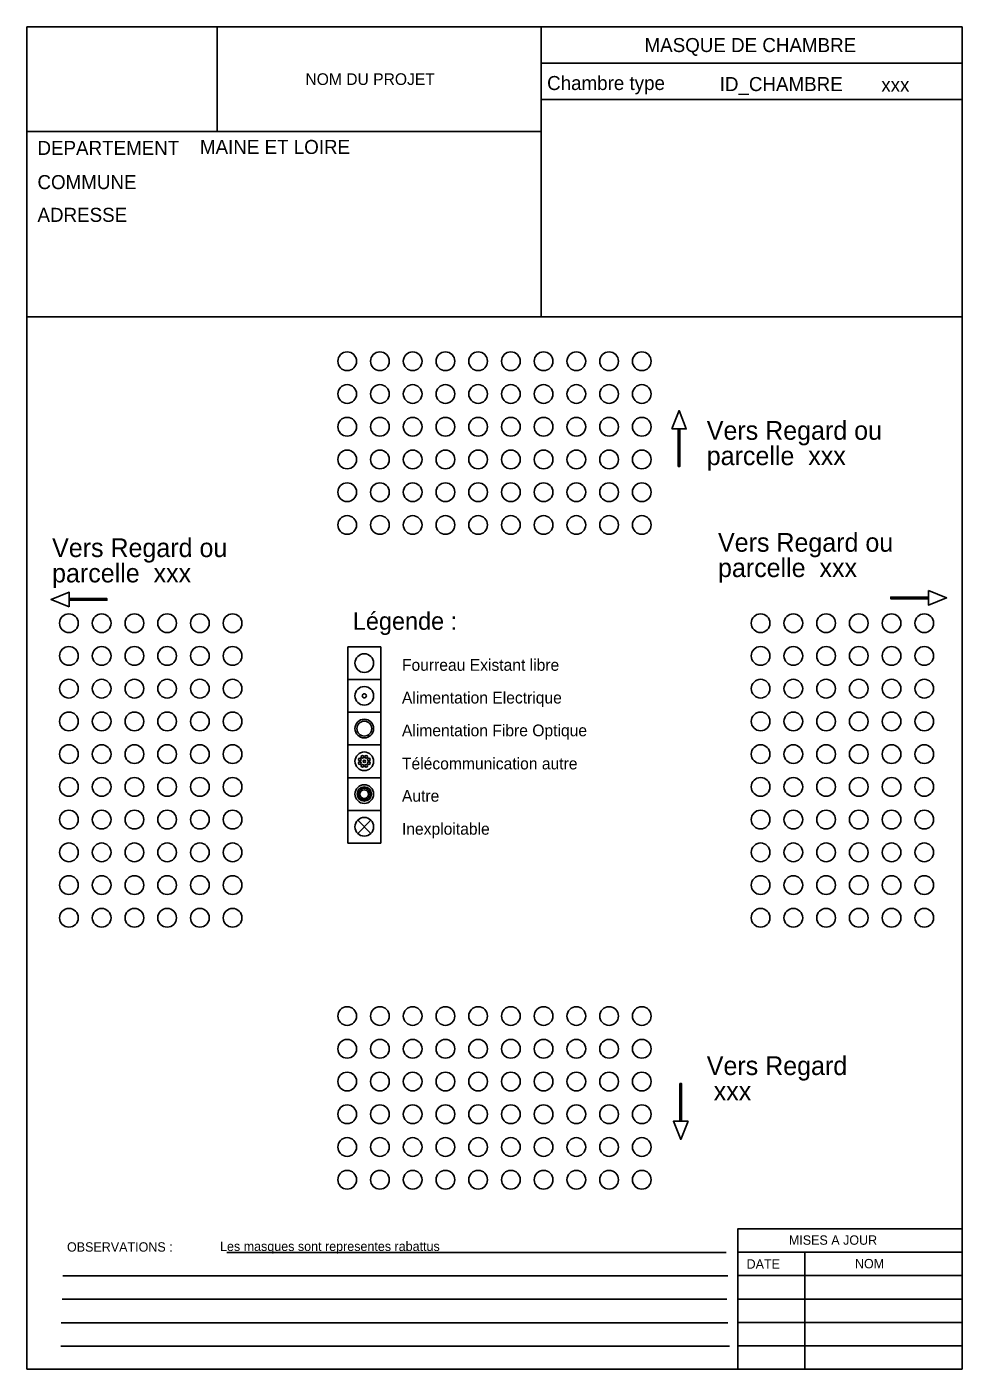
# Model space of a CAD drawing. Extents: x 10574.2 to 10614.2, y 48193.4 to 48250.8.
import ezdxf

# ---------------------------------------------------------------- set-up
doc = ezdxf.new("R2010")
doc.units = 0
doc.layers.add('GCV-détails', color=7, linetype='Continuous')

# ---------------------------------------------------------------- blocks, each defined once
blk = doc.blocks.new('Fourreau existant libre')
at = {"layer": 'GCV-détails'}
for p, q in [((0.7, 0.7), (-0.7, 0.7)), ((-0.7, 0.7), (-0.7, -0.7)), ((0.7, -0.7), (0.7, 0.7)), ((0.7, 0.7), (0.7, 0.7)), ((-0.7, -0.7), (0.7, -0.7))]:
    blk.add_line(p, q, dxfattribs=at)
blk.add_circle((0, 0), 0.4, dxfattribs=at)
blk = doc.blocks.new('Alimentation Fibre optique')
at = {"layer": 'GCV-détails'}
for p, q in [((0.7, 0.7), (-0.7, 0.7)), ((-0.7, 0.7), (-0.7, -0.7)), ((0.7, -0.7), (0.7, 0.7)), ((0.7, 0.7), (0.7, 0.7)), ((-0.7, -0.7), (0.7, -0.7))]:
    blk.add_line(p, q, dxfattribs=at)
for radius in [0.4, 0.318]:
    blk.add_circle((0, 0), radius, dxfattribs=at)
blk = doc.blocks.new('Alimentation Electrique')
at = {"layer": 'GCV-détails'}
for p, q in [((0.7, 0.7), (-0.7, 0.7)), ((-0.7, 0.7), (-0.7, -0.7)), ((0.7, -0.7), (0.7, 0.7)), ((0.7, 0.7), (0.7, 0.7)), ((-0.7, -0.7), (0.7, -0.7))]:
    blk.add_line(p, q, dxfattribs=at)
for radius in [0.4, 0.0885]:
    blk.add_circle((0, 0), radius, dxfattribs=at)
blk = doc.blocks.new('télécommunication autre')
at = {"layer": 'GCV-détails'}
for p, q in [((0.7, 0.7), (-0.7, 0.7)), ((-0.7, 0.7), (-0.7, -0.7)), ((0.7, -0.7), (0.7, 0.7)), ((0.7, 0.7), (0.7, 0.7)), ((-0.7, -0.7), (0.7, -0.7))]:
    blk.add_line(p, q, dxfattribs=at)
for centre, radius in [((0, 0), 0.4), ((-0.192, 0.079), 0.0541), ((-0.079, 0.192), 0.0541), ((0, 0), 0.0541), ((0.079, 0.192), 0.0541), ((0.192, 0.079), 0.0541), ((-0.192, -0.079), 0.0541), ((-0.079, -0.192), 0.0541), ((0.079, -0.192), 0.0541), ((0.192, -0.079), 0.0541)]:
    blk.add_circle(centre, radius, dxfattribs=at)
blk = doc.blocks.new('Autre')
at = {"layer": 'GCV-détails'}
for p, q in [((0.7, 0.7), (-0.7, 0.7)), ((-0.7, 0.7), (-0.7, -0.7)), ((0.7, -0.7), (0.7, 0.7)), ((0.7, 0.7), (0.7, 0.7)), ((-0.7, -0.7), (0.7, -0.7))]:
    blk.add_line(p, q, dxfattribs=at)
for radius in [0.4, 0.307, 0.251, 0.185]:
    blk.add_circle((0, 0), radius, dxfattribs=at)
blk = doc.blocks.new('Inexploitable')
at = {"layer": 'GCV-détails'}
for p, q in [((0.7, 0.7), (-0.7, 0.7)), ((-0.7, 0.7), (-0.7, -0.7)), ((0.7, -0.7), (0.7, 0.7)), ((0.7, 0.7), (0.7, 0.7)), ((-0.7, -0.7), (0.7, -0.7))]:
    blk.add_line(p, q, dxfattribs=at)
for points in [[(-0.283, 0.283), (0.283, -0.283)], [(-0.283, -0.283), (0.283, 0.283)]]:
    blk.add_lwpolyline(points, dxfattribs=at)
blk.add_circle((0, 0), 0.4, dxfattribs=at)
blk = doc.blocks.new('Fleche vers regard')
at = {"layer": 'GCV-détails'}
for points in [[(1.608, -0.036), (1.608, 0.036), (0, 0.036), (0, -0.036)], [(1.608, 0.312), (1.608, -0.312), (2.388, 0)]]:
    blk.add_lwpolyline(points, close=True, dxfattribs=at)

msp = doc.modelspace()

# ---------------------------------------------------------------- linework, layer by layer
at = {"layer": 'GCV-détails'}
for p, q in [((10607.507, 48193.396), (10607.507, 48198.396)), ((10604.283, 48194.384), (10575.691, 48194.384))]:
    msp.add_line(p, q, dxfattribs=at)
for points in [[(10574.233, 48193.396), (10614.233, 48193.396), (10614.233, 48250.796), (10574.233, 48250.796)], [(10582.366, 48246.323), (10596.233, 48246.323), (10596.233, 48250.796), (10582.366, 48250.796)], [(10596.233, 48249.24), (10614.233, 48249.24), (10614.233, 48250.796), (10596.233, 48250.796)], [(10596.233, 48238.396), (10614.233, 48238.396), (10614.233, 48249.24), (10596.233, 48249.24)], [(10596.233, 48247.684), (10614.233, 48247.684), (10614.233, 48249.24), (10596.233, 48249.24)], [(10574.233, 48238.396), (10596.233, 48238.396), (10596.233, 48246.323), (10574.233, 48246.323)], [(10604.633, 48193.396), (10614.233, 48193.396), (10614.233, 48199.396), (10604.633, 48199.396)]]:
    msp.add_lwpolyline(points, close=True, dxfattribs=at)
for points in [[(10582.783, 48198.384), (10604.137, 48198.384)], [(10604.633, 48198.396), (10614.233, 48198.396)], [(10575.775, 48197.384), (10604.175, 48197.384), (10604.211, 48197.384)], [(10604.633, 48197.396), (10614.233, 48197.396)], [(10575.741, 48196.384), (10604.175, 48196.384)], [(10604.633, 48196.396), (10614.233, 48196.396)], [(10575.705, 48195.384), (10604.211, 48195.384)], [(10604.633, 48195.396), (10604.633, 48195.396), (10614.233, 48195.396)], [(10604.633, 48194.396), (10614.233, 48194.396)]]:
    msp.add_lwpolyline(points, dxfattribs=at)
for centre in [(10587.933, 48236.496), (10589.333, 48236.496), (10590.733, 48236.496), (10592.133, 48236.496), (10593.533, 48236.496), (10594.933, 48236.496), (10596.333, 48236.496), (10597.733, 48236.496), (10599.133, 48236.496), (10600.533, 48236.496), (10587.933, 48235.096), (10589.333, 48235.096), (10590.733, 48235.096), (10592.133, 48235.096), (10593.533, 48235.096), (10594.933, 48235.096), (10596.333, 48235.096), (10597.733, 48235.096), (10599.133, 48235.096), (10600.533, 48235.096), (10587.933, 48233.696), (10589.333, 48233.696), (10590.733, 48233.696), (10592.133, 48233.696), (10593.533, 48233.696), (10594.933, 48233.696), (10596.333, 48233.696), (10597.733, 48233.696), (10599.133, 48233.696), (10600.533, 48233.696), (10587.933, 48232.296), (10589.333, 48232.296), (10590.733, 48232.296), (10592.133, 48232.296), (10593.533, 48232.296), (10594.933, 48232.296), (10596.333, 48232.296), (10597.733, 48232.296), (10599.133, 48232.296), (10600.533, 48232.296), (10587.933, 48230.896), (10589.333, 48230.896), (10590.733, 48230.896), (10592.133, 48230.896), (10593.533, 48230.896), (10594.933, 48230.896), (10596.333, 48230.896), (10597.733, 48230.896), (10599.133, 48230.896), (10600.533, 48230.896), (10587.933, 48229.496), (10589.333, 48229.496), (10590.733, 48229.496), (10592.133, 48229.496), (10593.533, 48229.496), (10594.933, 48229.496), (10596.333, 48229.496), (10597.733, 48229.496), (10599.133, 48229.496), (10600.533, 48229.496), (10576.033, 48225.296), (10577.433, 48225.296), (10578.833, 48225.296), (10580.233, 48225.296), (10581.633, 48225.296), (10583.033, 48225.296), (10605.614, 48225.296), (10607.014, 48225.296), (10608.414, 48225.296), (10609.814, 48225.296), (10611.214, 48225.296), (10612.614, 48225.296), (10576.033, 48223.896), (10577.433, 48223.896), (10578.833, 48223.896), (10580.233, 48223.896), (10581.633, 48223.896), (10583.033, 48223.896), (10605.614, 48223.896), (10607.014, 48223.896), (10608.414, 48223.896), (10609.814, 48223.896), (10611.214, 48223.896), (10612.614, 48223.896), (10576.033, 48222.496), (10577.433, 48222.496), (10578.833, 48222.496), (10580.233, 48222.496), (10581.633, 48222.496), (10583.033, 48222.496), (10605.614, 48222.496), (10607.014, 48222.496), (10608.414, 48222.496), (10609.814, 48222.496), (10611.214, 48222.496), (10612.614, 48222.496), (10576.033, 48221.096), (10577.433, 48221.096), (10578.833, 48221.096), (10580.233, 48221.096), (10581.633, 48221.096), (10583.033, 48221.096), (10605.614, 48221.096), (10607.014, 48221.096), (10608.414, 48221.096), (10609.814, 48221.096), (10611.214, 48221.096), (10612.614, 48221.096), (10576.033, 48219.696), (10577.433, 48219.696), (10578.833, 48219.696), (10580.233, 48219.696), (10581.633, 48219.696), (10583.033, 48219.696), (10605.614, 48219.696), (10607.014, 48219.696), (10608.414, 48219.696), (10609.814, 48219.696), (10611.214, 48219.696), (10612.614, 48219.696), (10576.033, 48218.296), (10577.433, 48218.296), (10578.833, 48218.296), (10580.233, 48218.296), (10581.633, 48218.296), (10583.033, 48218.296), (10605.614, 48218.296), (10607.014, 48218.296), (10608.414, 48218.296), (10609.814, 48218.296), (10611.214, 48218.296), (10612.614, 48218.296), (10576.033, 48216.896), (10577.433, 48216.896), (10578.833, 48216.896), (10580.233, 48216.896), (10581.633, 48216.896), (10583.033, 48216.896), (10605.614, 48216.896), (10607.014, 48216.896), (10608.414, 48216.896), (10609.814, 48216.896), (10611.214, 48216.896), (10612.614, 48216.896), (10576.033, 48215.496), (10577.433, 48215.496), (10578.833, 48215.496), (10580.233, 48215.496), (10581.633, 48215.496), (10583.033, 48215.496), (10605.614, 48215.496), (10607.014, 48215.496), (10608.414, 48215.496), (10609.814, 48215.496), (10611.214, 48215.496), (10612.614, 48215.496), (10576.033, 48214.096), (10577.433, 48214.096), (10578.833, 48214.096), (10580.233, 48214.096), (10581.633, 48214.096), (10583.033, 48214.096), (10605.614, 48214.096), (10607.014, 48214.096), (10608.414, 48214.096), (10609.814, 48214.096), (10611.214, 48214.096), (10612.614, 48214.096), (10576.033, 48212.696), (10577.433, 48212.696), (10578.833, 48212.696), (10580.233, 48212.696), (10581.633, 48212.696), (10583.033, 48212.696), (10605.614, 48212.696), (10607.014, 48212.696), (10608.414, 48212.696), (10609.814, 48212.696), (10611.214, 48212.696), (10612.614, 48212.696), (10587.933, 48208.496), (10589.333, 48208.496), (10590.733, 48208.496), (10592.133, 48208.496), (10593.533, 48208.496), (10594.933, 48208.496), (10596.333, 48208.496), (10597.733, 48208.496), (10599.133, 48208.496), (10600.533, 48208.496), (10587.933, 48207.096), (10589.333, 48207.096), (10590.733, 48207.096), (10592.133, 48207.096), (10593.533, 48207.096), (10594.933, 48207.096), (10596.333, 48207.096), (10597.733, 48207.096), (10599.133, 48207.096), (10600.533, 48207.096), (10587.933, 48205.696), (10589.333, 48205.696), (10590.733, 48205.696), (10592.133, 48205.696), (10593.533, 48205.696), (10594.933, 48205.696), (10596.333, 48205.696), (10597.733, 48205.696), (10599.133, 48205.696), (10600.533, 48205.696), (10587.933, 48204.296), (10589.333, 48204.296), (10590.733, 48204.296), (10592.133, 48204.296), (10593.533, 48204.296), (10594.933, 48204.296), (10596.333, 48204.296), (10597.733, 48204.296), (10599.133, 48204.296), (10600.533, 48204.296), (10587.933, 48202.896), (10589.333, 48202.896), (10590.733, 48202.896), (10592.133, 48202.896), (10593.533, 48202.896), (10594.933, 48202.896), (10596.333, 48202.896), (10597.733, 48202.896), (10599.133, 48202.896), (10600.533, 48202.896), (10587.933, 48201.496), (10589.333, 48201.496), (10590.733, 48201.496), (10592.133, 48201.496), (10593.533, 48201.496), (10594.933, 48201.496), (10596.333, 48201.496), (10597.733, 48201.496), (10599.133, 48201.496), (10600.533, 48201.496)]:
    msp.add_circle(centre, 0.4, dxfattribs=at)

# ---------------------------------------------------------------- block references
for p, rotation in [((10602.125, 48231.998), 90), ((10577.658, 48226.309), 180), ((10602.197, 48205.606), -90.00000000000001)]:
    msp.add_blockref('Fleche vers regard', p, dxfattribs=dict(rotation=rotation))
for name, p in [('Fleche vers regard', (10611.181, 48226.379)), ('Fourreau existant libre', (10588.665, 48223.589)), ('Alimentation Electrique', (10588.665, 48222.189)), ('Alimentation Fibre optique', (10588.665, 48220.789)), ('télécommunication autre', (10588.665, 48219.389)), ('Autre', (10588.665, 48217.989)), ('Inexploitable', (10588.665, 48216.589))]:
    msp.add_blockref(name, p)

# ---------------------------------------------------------------- texts
for s, height, p in [('MASQUE DE CHAMBRE', 0.6, (10600.65, 48249.718)), ('NOM DU PROJET', 0.5, (10586.147, 48248.31)), ('Chambre type', 0.6, (10596.483, 48248.094)), ('ID_CHAMBRE', 0.6, (10603.865, 48248.05)), ('xxx', 0.6, (10610.775, 48248.02)), ('DEPARTEMENT', 0.6, (10574.688, 48245.318)), ('MAINE ET LOIRE', 0.6, (10581.636, 48245.361)), ('COMMUNE', 0.6, (10574.688, 48243.857)), ('ADRESSE', 0.6, (10574.688, 48242.457)), ('Vers Regard ou', 0.8, (10603.311, 48233.138)), ('parcelle  xxx', 0.8, (10603.311, 48232.055)), ('Vers Regard ou', 0.8, (10575.313, 48228.123)), ('Vers Regard ou', 0.8, (10603.792, 48228.351)), ('parcelle  xxx', 0.8, (10603.792, 48227.267)), ('parcelle  xxx', 0.8, (10575.313, 48227.039)), ('Légende :', 0.75, (10588.175, 48225.013)), ('Fourreau Existant libre', 0.5, (10590.275, 48223.259)), ('Alimentation Electrique', 0.5, (10590.275, 48221.861)), ('Alimentation Fibre Optique', 0.5, (10590.275, 48220.461)), ('Télécommunication autre', 0.5, (10590.275, 48219.043)), ('Autre', 0.5, (10590.275, 48217.662)), ('Inexploitable', 0.5, (10590.275, 48216.251)), ('Vers Regard', 0.8, (10603.311, 48205.973)), (' xxx', 0.8, (10603.311, 48204.889)), ('OBSERVATIONS :', 0.4, (10575.951, 48198.422)), ('Les masques sont representes rabattus', 0.4, (10582.495, 48198.45)), ('MISES A JOUR', 0.4, (10606.823, 48198.716)), ('DATE', 0.4, (10605.015, 48197.694)), ('NOM', 0.4, (10609.649, 48197.708))]:
    msp.add_text(s, height=height, dxfattribs=at).set_placement(p)

doc.saveas('drawing.dxf')
